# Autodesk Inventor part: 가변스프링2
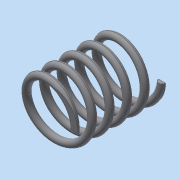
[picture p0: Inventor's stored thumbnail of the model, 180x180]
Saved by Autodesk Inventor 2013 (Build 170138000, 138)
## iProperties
Created: 2018-10
Part Number: 가변스프링2
Material: 일반
Document SubType Name: Modeling
Designer: Administrator
Density: 1 g/cm^3
Author: Administrator
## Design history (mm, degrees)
sketch "스케치1"
  geometry: L1 (0, 0)-(0, 24.744); L2 (0, 0)-(8, 0); L3 (0, 24.744)-(8, 24.744); C1 r 1 at (8, 0)
  constraints: 6 end point, 1 centre point, 1 coincident, 1 parallel, 1 perpendicular, 1 vertical
  dimensions: "d0" = 24.74445 distance of L1.start L1.end (derived); "d3" = 8 distance of L1.start L2.end; "d4" = 2 diameter of C1; "d5" = 8 distance of L1.end L3.end
feature "코일1" sketch "스케치1" pitch "d6" = 10; turns "d8" = 5; dims "d7" = 24.74445 (= d0), "d9" = 0, angle "d10" = 90 deg, angle "d11" = 90 deg, "d12" = 0, "d13" = 0
sketch "스케치2"
  geometry: L1 (24.744, 10)-(0, 10); L2 (0, 10)-(0, -10); L3 (0, -10)-(24.744, -10); L4 (24.744, -10)-(24.744, 10); 2 further points
  constraints: 8 end point, 2 parallel, 1 coincident, 1 horizontal, 1 midpoint, 1 perpendicular
  dimensions: "d14" = 24.74445 distance of L2.end L3.end (derived); "d16" = 20 distance of L3.end L1.start
extrude "돌출1" sketch "스케치2" stored distance "d17" = 0; taper "d18" = 0 deg
node "솔리드1"
